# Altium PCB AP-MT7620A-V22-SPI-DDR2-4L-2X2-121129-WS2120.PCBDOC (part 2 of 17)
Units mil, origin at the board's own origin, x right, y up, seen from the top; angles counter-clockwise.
Board outline 7316 x 4279 mil, 4 copper layers (Top, Inner Layer 2, Inner Layer 3, Bottom), stack 35.4 mil thick; 640 components, 473 nets, 2041 pads, 2358 vias.
Unrouted connection lines stored in the file: 11.
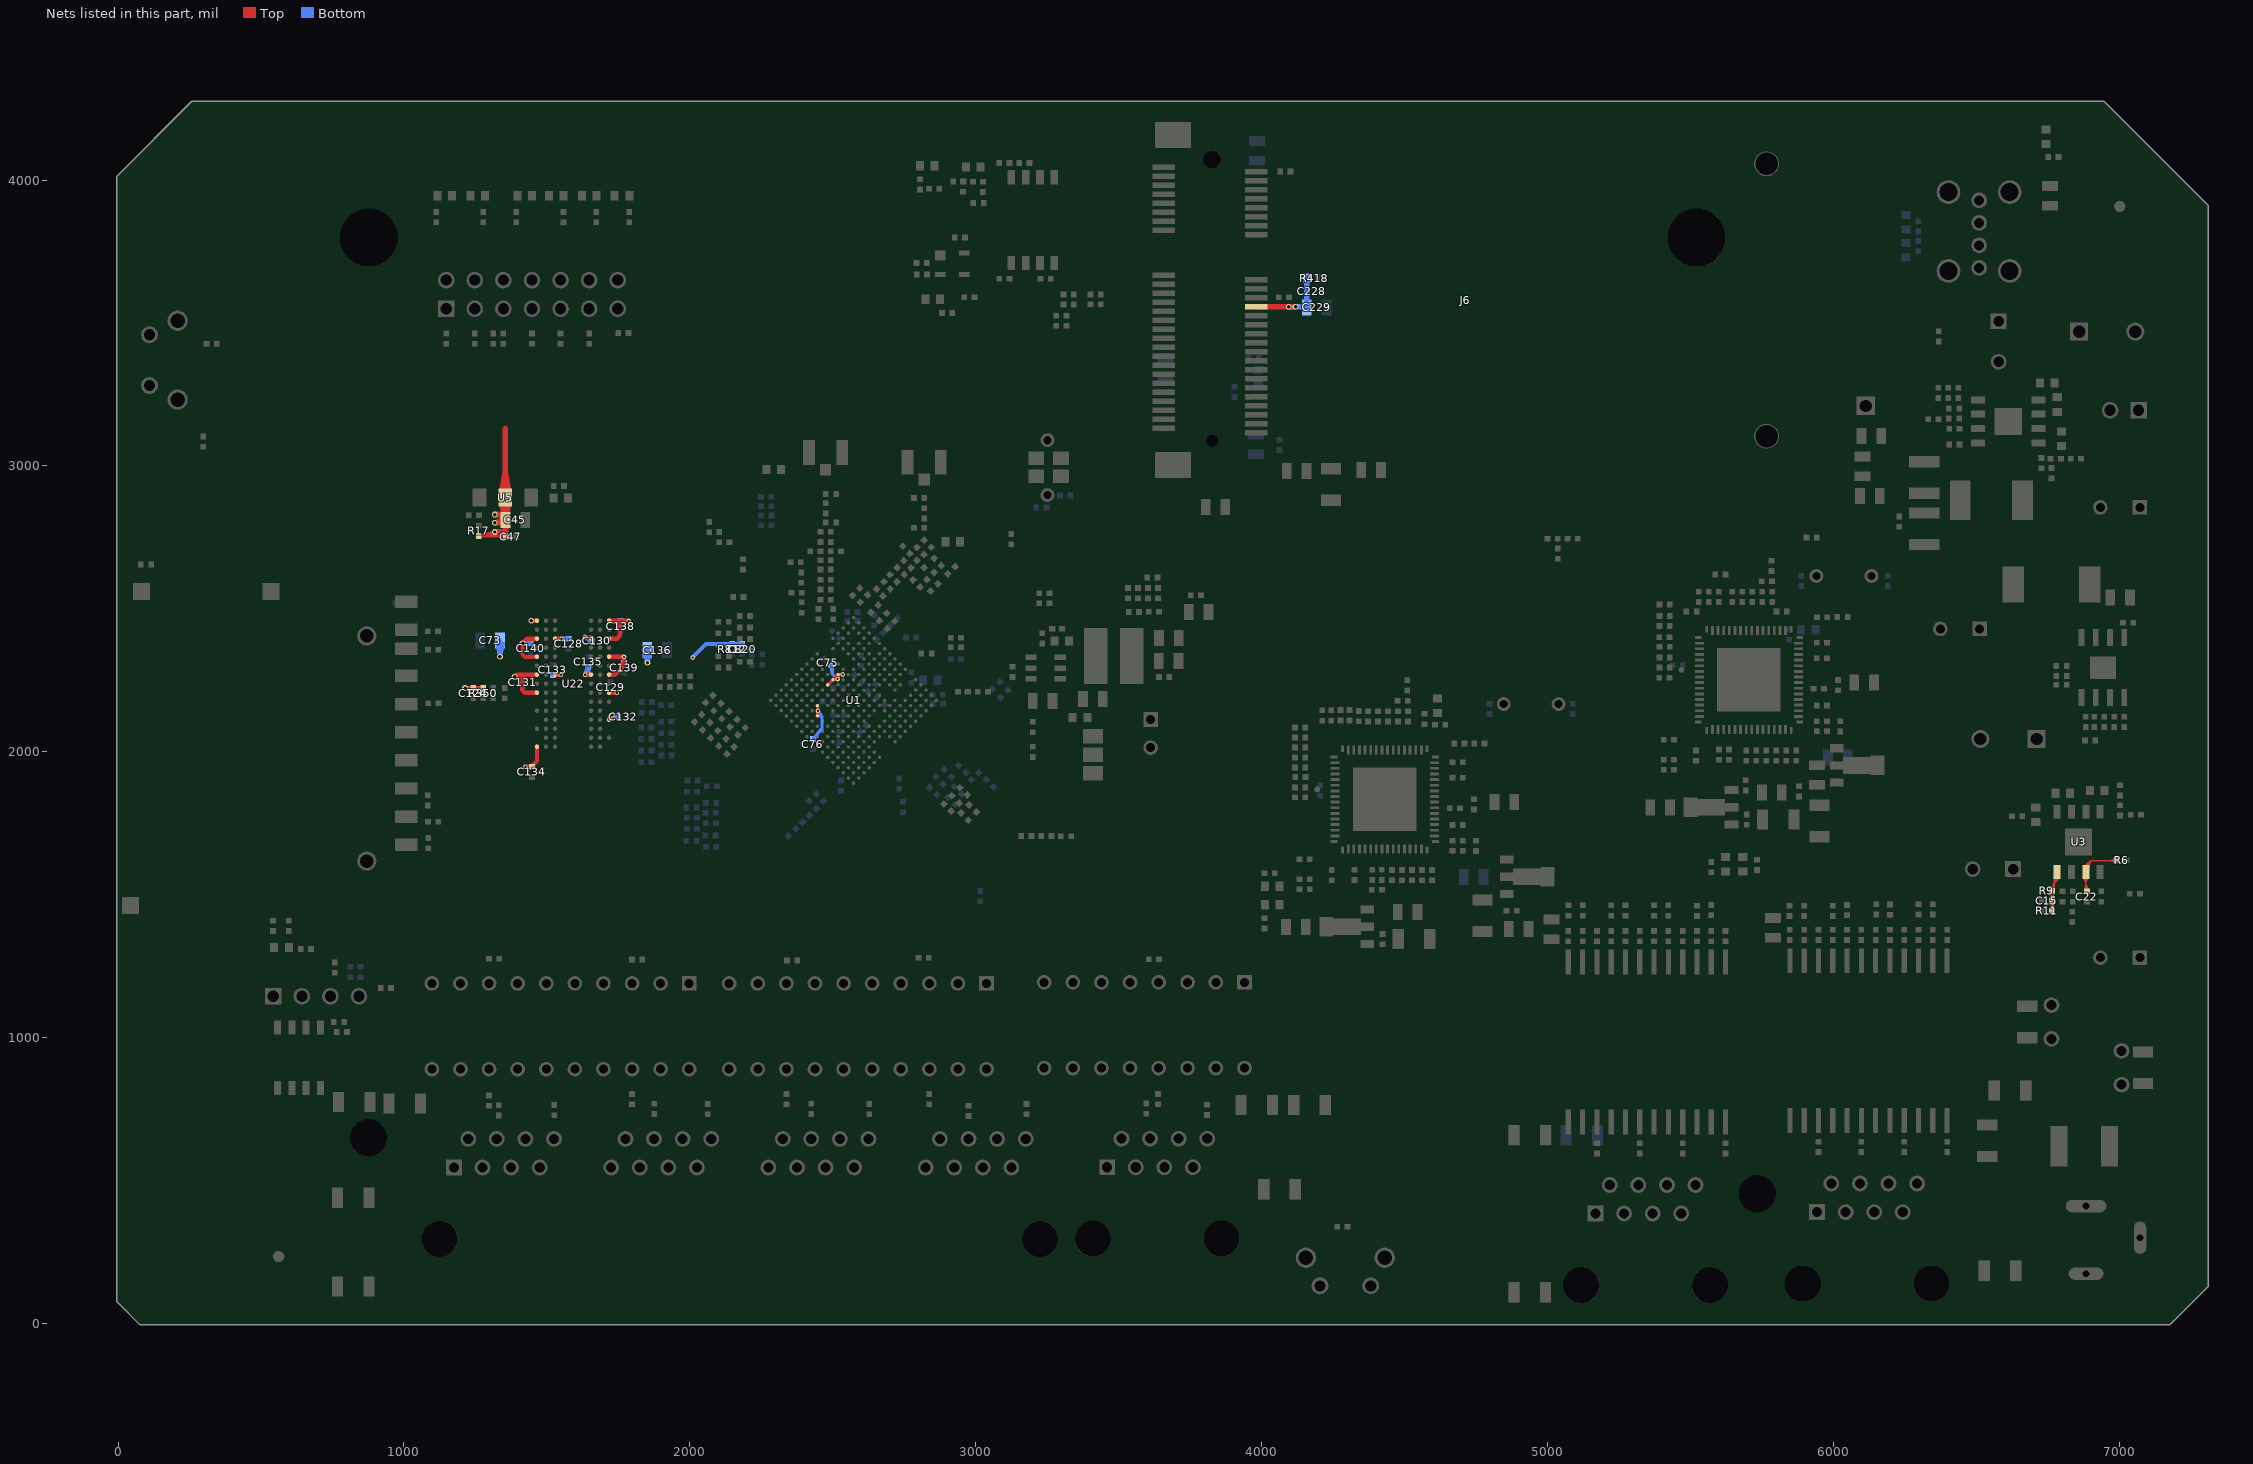
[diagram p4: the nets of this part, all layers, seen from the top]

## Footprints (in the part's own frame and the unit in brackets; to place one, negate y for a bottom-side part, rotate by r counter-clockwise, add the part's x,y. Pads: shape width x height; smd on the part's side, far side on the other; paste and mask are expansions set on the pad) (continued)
CON10P/SMD/R/F/7SDCN-B0-1X14 [mm]
  rect 1.1x2 smd: 1(-2.5,0) 2(-5,0) 3(-7.5,0) 4(-10,0) 5(-12.5,0) 6(-15,0) 7(-17.4,0) 8(-19.1,0) 9(0,0) CD(-21.6,0)
  rect 1.5x1.5 smd: GND1(-22.5,-12) GND2(5.4,-24.5) WP(-22.5,-23.5)
  round 1.7 hole 1.2 unplated: H1(-18.55,-3.5) H2(1.45,-3.5)
  silkscreen extent -22.95,-25.6 5.65,0.1
CRYS/DIP/D5X10.6/GB2000025/ECERA [mm]
  round 1.23 hole 0.73: 1(-2.44,0) 2(2.44,0)
  silkscreen extent -5.79,-2.62 5.79,2.62
CRYS/SMD/D3.2X2.5/E3SB40/HOSONIC [mm]
  rect 1.4x1.2 smd: 1(-1.1,-0.8) 2(1.1,-0.8) 3(1.1,0.8) 4(-1.1,0.8)
  silkscreen extent -2,-1.6 1.7,1.35
D/SMD/P6.61/B540C [mm]
  rect 1.92x3.18 smd: 1(-3.405,0) 2(3.405,0)
  silkscreen extent -3.55,-3.21 3.55,3.21
DC-JACK/3P/DIP/R/JD003-PF [mm]
  oval 3.1x1.1 hole 0.6 slot 2.6 at 0 deg: 1(0,-6)
  oval 1.1x2.9 hole 0.6 slot 2.4 at 0 deg: 2(4.8,-2.8)
  oval 3.6x1.1 hole 0.6 slot 3.1 at 0 deg: 3(0,0)
  silkscreen extent -4.6,-13.9 4.6,0.8
DIP2/P2.54 [mil]
  rect 58x58 hole 39: 1(0,0)
  round 58 hole 39: 2(100,0)
  silkscreen extent -60,-50 150,60
DIP4/P2.54 [mil]
  rect 58x58 hole 39: 1(0,0)
  round 58 hole 39: 2(100,0) 3(200,0) 4(300,0)
  silkscreen extent -60,-50 350,60
DIP7X2/P2.54 [mil]
  rect 58x58 hole 39: 1(0,0)
  round 58 hole 39: 2(0,100) 3(100,0) 4(100,100) 5(200,0) 6(200,100) 7(300,0) 8(300,100) 9(400,0) 10(400,100) 11(500,0) 12(500,100) 13(600,0) 14(600,100)
  silkscreen extent -50,-60 650,160
FD [mm]
  round 1 smd: 1(0,0)
  Top pour cut-out: 1.169,0 1.167,0.057 1.163,0.115 1.156,0.171 1.146,0.228 1.134,0.284 1.118,0.339 1.1,0.394 1.08,0.447 1.057,0.5 1.031,0.551 1.002,0.601 0.972,0.649 0.939,0.696 0.903,0.741 0.866,0.785 0.826,0.826 0.785,0.866 0.741,0.903 0.696,0.939 0.649,0.972 0.601,1.002 0.551,1.031 0.5,1.057 0.447,1.08 0.394,1.1 0.339,1.118 0.284,1.134 0.228,1.146 0.171,1.156 0.115,1.163 0.057,1.167 0,1.169 -0.057,1.167 -0.115,1.163 -0.171,1.156 -0.228,1.146 -0.284,1.134 -0.339,1.118 -0.394,1.1 -0.447,1.08 -0.5,1.057 -0.551,1.031 -0.601,1.002 -0.649,0.972 -0.696,0.939 -0.741,0.903 -0.785,0.866 -0.826,0.826 -0.866,0.785 -0.903,0.741 -0.939,0.696 -0.972,0.649 -1.002,0.601 -1.031,0.551 -1.057,0.5 -1.08,0.447 -1.1,0.394 -1.118,0.339 -1.134,0.284 -1.146,0.228 -1.156,0.171 -1.163,0.115 -1.167,0.057 -1.169,0 -1.167,-0.057 -1.163,-0.115 -1.156,-0.171 -1.146,-0.228 -1.134,-0.284 -1.118,-0.339 -1.1,-0.394 -1.08,-0.447 -1.057,-0.5 -1.031,-0.551 -1.002,-0.601 -0.972,-0.649 -0.939,-0.696 -0.903,-0.741 -0.866,-0.785 -0.826,-0.826 -0.785,-0.866 -0.741,-0.903 -0.696,-0.939 -0.649,-0.972 -0.601,-1.002 -0.551,-1.031 -0.5,-1.057 -0.447,-1.08 -0.394,-1.1 -0.339,-1.118 -0.284,-1.134 -0.228,-1.146 -0.171,-1.156 -0.115,-1.163 -0.057,-1.167 0,-1.169 0.057,-1.167 0.115,-1.163 0.171,-1.156 0.228,-1.146 0.284,-1.134 0.339,-1.118 0.394,-1.1 0.447,-1.08 0.5,-1.057 0.551,-1.031 0.601,-1.002 0.649,-0.972 0.696,-0.939 0.741,-0.903 0.785,-0.866 0.826,-0.826 0.866,-0.785 0.903,-0.741 0.939,-0.696 0.972,-0.649 1.002,-0.601 1.031,-0.551 1.057,-0.5 1.08,-0.447 1.1,-0.394 1.118,-0.339 1.134,-0.284 1.146,-0.228 1.156,-0.171 1.163,-0.115 1.167,-0.057 1.169,0
L0402 [mil]
  rect 20x20 smd: 1(-18,0) 2(18,0)
  silkscreen extent -33,-15 33,15
L0805 [mil]
  rect 34x56 smd: 1(-34.45,0) 2(34.45,0)
  silkscreen extent -63,-38 63,38
L1206 [mm]
  rect 1x1.8 smd: 1(-1.4,0) 2(1.4,0)
  silkscreen extent -2.2,-1.2 2.2,1.2
L/IND/DIP/D6H14 [mil]
  round 55 hole 35: 1(-59.06,0) 2(59.06,0)
  Keep-Out Layer pour cut-out: 202 vertices and 0 holes, not listed, extent -116.12,-118.12 120.12,118.12
  silkscreen extent -118,-123 121,123
L/IND/DIP/MCD-0808-150MU-J [mm]
  rect 1.6x1.6 hole 1.1: 1(-2.5,0)
  round 1.6 hole 1.1: 2(2.5,0)
  silkscreen extent -5.35,-5.35 5.35,5.35
L/IND/SMD/GSTD6030PW-6R8M [mm]
  rect 1.85x3.5 smd: 1(-2.775,0) 2(2.775,0)
  silkscreen extent -3.55,-3.55 3.55,3.45
L/IND/SMD/LVS5045 [mm]
  rect 2.1x5 smd: 1(-1.6,0) 2(1.6,0)
  Top pour cut-out: -0.556,2.507 0.551,2.507 0.551,-2.504 -0.556,-2.504 -0.556,2.507
  silkscreen extent -2.6,-2.6 2.6,2.6
MINI-PCI-EXPRESS/52P/SMD/R/F/C1720007 [mm]
  rect 0.5x2 smd: 1(0,0) 2(0.4,8.2) 3(0.8,0) 4(1.2,8.2) 5(1.6,0) 6(2,8.2) 7(2.4,0) 8(2.8,8.2) 9(3.2,0) 10(3.6,8.2) 11(4,0) 12(4.4,8.2) 13(4.8,0) 14(5.2,8.2) 15(5.6,0) 16(6,8.2) 17(9.6,0) 18(10,8.2) 19(10.4,0) 20(10.8,8.2) 21(11.2,0) 22(11.6,8.2) 23(12,0) 24(12.4,8.2) 25(12.8,0) 26(13.2,8.2) 27(13.6,0) 28(14,8.2) 29(14.4,0) 30(14.8,8.2) 31(15.2,0) 32(15.6,8.2) 33(16,0) 34(16.4,8.2) 35(16.8,0) 36(17.2,8.2) 37(17.6,0) 38(18,8.2) 39(18.4,0) 40(18.8,8.2) 41(19.2,0) 42(19.6,8.2) 43(20,0) 44(20.4,8.2) 45(20.8,0) 46(21.2,8.2) 47(21.6,0) 48(22,8.2) 49(22.4,0) 50(22.8,8.2) 51(23.2,0) 52(23.6,8.2)
  rect 2.3x3.2 smd: 53(-2.85,0.8) 54(26.45,0.8)
  round 1.6 hole 1.6 unplated: 55(-0.7,4.3)
  round 1.1 hole 1.1 unplated: 56(24.3,4.3)
  round 2.2 hole 2: 57(-0.3,53.55)
  round 2.2 / inner round 2.2 / far side round 2 hole 2: 58(23.9,53.55)
  Top region: -3.2,49.454 2.515,49.454 2.515,55.397 21.082,55.397 21.082,49.454 26.822,49.454 26.822,59.741 15.824,59.741 15.824,57.252 13.564,57.252 13.564,59.741 10.033,59.741 10.033,57.252 7.747,57.252 7.747,59.741 -3.2,59.741 -3.2,49.454
  Keep-Out Layer pour cut-out: 25.104,4.3 25.103,4.349 25.098,4.397 25.091,4.445 25.081,4.492 25.068,4.539 25.052,4.585 25.034,4.63 25.012,4.674 24.988,4.716 24.962,4.757 24.933,4.796 24.902,4.833 24.869,4.869 24.833,4.902 24.796,4.933 24.757,4.962 24.716,4.988 24.674,5.012 24.63,5.034 24.585,5.052 24.539,5.068 24.492,5.081 24.445,5.091 24.397,5.098 24.349,5.103 24.3,5.104 24.251,5.103 24.203,5.098 24.155,5.091 24.108,5.081 24.061,5.068 24.015,5.052 23.97,5.034 23.926,5.012 23.884,4.988 23.843,4.962 23.804,4.933 23.767,4.902 23.731,4.869 23.698,4.833 23.667,4.796 23.638,4.757 23.612,4.716 23.588,4.674 23.566,4.63 23.548,4.585 23.532,4.539 23.519,4.492 23.509,4.445 23.501,4.397 23.497,4.349 23.496,4.3 23.497,4.251 23.501,4.203 23.509,4.155 23.519,4.108 23.532,4.061 23.548,4.015 23.566,3.97 23.588,3.926 23.612,3.884 23.638,3.843 23.667,3.804 23.698,3.767 23.731,3.731 23.767,3.698 23.804,3.667 23.843,3.638 23.884,3.612 23.926,3.588 23.97,3.566 24.015,3.548 24.061,3.532 24.108,3.519 24.155,3.509 24.203,3.501 24.251,3.497 24.3,3.496 24.349,3.497 24.397,3.501 24.445,3.509 24.492,3.519 24.539,3.532 24.585,3.548 24.63,3.566 24.674,3.588 24.716,3.612 24.757,3.638 24.796,3.667 24.833,3.698 24.869,3.731 24.902,3.767 24.933,3.804 24.962,3.843 24.988,3.884 25.012,3.926 25.034,3.97 25.052,4.015 25.068,4.061 25.081,4.108 25.091,4.155 25.098,4.203 25.103,4.251 25.104,4.3
  Keep-Out Layer pour cut-out: 0.354,4.3 0.353,4.355 0.349,4.41 0.341,4.465 0.331,4.519 0.318,4.573 0.303,4.626 0.284,4.678 0.263,4.729 0.239,4.779 0.213,4.827 0.184,4.874 0.153,4.92 0.119,4.964 0.084,5.006 0.046,5.046 0.006,5.084 -0.036,5.119 -0.08,5.153 -0.126,5.184 -0.173,5.213 -0.221,5.239 -0.271,5.263 -0.322,5.284 -0.374,5.303 -0.427,5.318 -0.481,5.331 -0.535,5.341 -0.59,5.349 -0.645,5.353 -0.7,5.354 -0.755,5.353 -0.81,5.349 -0.865,5.341 -0.919,5.331 -0.973,5.318 -1.026,5.303 -1.078,5.284 -1.129,5.263 -1.179,5.239 -1.227,5.213 -1.274,5.184 -1.32,5.153 -1.364,5.119 -1.406,5.084 -1.446,5.046 -1.484,5.006 -1.519,4.964 -1.553,4.92 -1.584,4.874 -1.613,4.827 -1.639,4.779 -1.663,4.729 -1.684,4.678 -1.703,4.626 -1.718,4.573 -1.731,4.519 -1.741,4.465 -1.749,4.41 -1.753,4.355 -1.754,4.3 -1.753,4.245 -1.749,4.19 -1.741,4.135 -1.731,4.081 -1.718,4.027 -1.703,3.974 -1.684,3.922 -1.663,3.871 -1.639,3.821 -1.613,3.773 -1.584,3.726 -1.553,3.68 -1.519,3.636 -1.484,3.594 -1.446,3.554 -1.406,3.516 -1.364,3.481 -1.32,3.447 -1.274,3.416 -1.227,3.387 -1.179,3.361 -1.129,3.337 -1.078,3.316 -1.026,3.297 -0.973,3.282 -0.919,3.269 -0.865,3.259 -0.81,3.251 -0.755,3.247 -0.7,3.246 -0.645,3.247 -0.59,3.251 -0.535,3.259 -0.481,3.269 -0.427,3.282 -0.374,3.297 -0.322,3.316 -0.271,3.337 -0.221,3.361 -0.173,3.387 -0.126,3.416 -0.08,3.447 -0.036,3.481 0.006,3.516 0.046,3.554 0.084,3.594 0.119,3.636 0.153,3.68 0.184,3.726 0.213,3.773 0.239,3.821 0.263,3.871 0.284,3.922 0.303,3.974 0.318,4.027 0.331,4.081 0.341,4.135 0.349,4.19 0.353,4.245 0.354,4.3
  silkscreen extent -4.5,-1.7 28,60.2
MT7620AE2/TFBGA265/P0.65/B0.3/11X11 [mm]
  round 0.3 smd: A1(-5.2,5.2) A2(-4.55,5.2) A3(-3.9,5.2) A4(-3.25,5.2) A5(-2.6,5.2) A6(-1.95,5.2) A7(-1.3,5.2) A8(-0.65,5.2) A9(0,5.2) A10(0.65,5.2) A11(1.3,5.2) A13(2.6,5.2) A14(3.25,5.2) A15(3.9,5.2) A16(4.55,5.2) A17(5.2,5.2) B1(-5.2,4.55) B2(-4.55,4.55) B3(-3.9,4.55) B4(-3.25,4.55) B5(-2.6,4.55) B7(-1.3,4.55) B8(-0.65,4.55) B9(0,4.55) B10(0.65,4.55) B11(1.3,4.55) B14(3.25,4.55) B15(3.9,4.55) B16(4.55,4.55) B17(5.2,4.55) C1(-5.2,3.9) C2(-4.55,3.9) C4(-3.25,3.9) C5(-2.6,3.9) C6(-1.95,3.9) C7(-1.3,3.9) C8(-0.65,3.9) C9(0,3.9) C10(0.65,3.9) C11(1.3,3.9) C12(1.95,3.9) C14(3.25,3.9) C15(3.9,3.9) C16(4.55,3.9) C17(5.2,3.9) D1(-5.2,3.25) D2(-4.55,3.25) D3(-3.9,3.25) D4(-3.25,3.25) D5(-2.6,3.25) D6(-1.95,3.25) D7(-1.3,3.25) D8(-0.65,3.25) D9(0,3.25) D10(0.65,3.25) D11(1.3,3.25) D12(1.95,3.25) D14(3.25,3.25) D15(3.9,3.25) D16(4.55,3.25) D17(5.2,3.25) E1(-5.2,2.6) E2(-4.55,2.6) E3(-3.9,2.6) E4(-3.25,2.6) E5(-2.6,2.6) E6(-1.95,2.6) E7(-1.3,2.6) E8(-0.65,2.6) E9(0,2.6) E10(0.65,2.6) E13(2.6,2.6) E14(3.25,2.6) E15(3.9,2.6) E16(4.55,2.6) E17(5.2,2.6) F2(-4.55,1.95) F6(-1.95,1.95) F7(-1.3,1.95) F8(-0.65,1.95) F9(0,1.95) F10(0.65,1.95) F11(1.3,1.95) F12(1.95,1.95) F13(2.6,1.95) F14(3.25,1.95) F15(3.9,1.95) F16(4.55,1.95) F17(5.2,1.95) G4(-3.25,1.3) G5(-2.6,1.3) G6(-1.95,1.3) G7(-1.3,1.3) G8(-0.65,1.3) G9(0,1.3) G10(0.65,1.3) G11(1.3,1.3) G12(1.95,1.3) G13(2.6,1.3) G14(3.25,1.3) G15(3.9,1.3) G16(4.55,1.3) G17(5.2,1.3) H1(-5.2,0.65) H2(-4.55,0.65) H3(-3.9,0.65) H4(-3.25,0.65) H5(-2.6,0.65) H6(-1.95,0.65) H7(-1.3,0.65) H8(-0.65,0.65) H9(0,0.65) H10(0.65,0.65) H11(1.3,0.65) H12(1.95,0.65) H14(3.25,0.65) H15(3.9,0.65) H16(4.55,0.65) H17(5.2,0.65) J1(-5.2,0) J2(-4.55,0) J3(-3.9,0) J4(-3.25,0) J5(-2.6,0) J6(-1.95,0) J7(-1.3,0) J8(-0.65,0) J9(0,0) J10(0.65,0) J11(1.3,0) J12(1.95,0) J14(3.25,0) J15(3.9,0) J16(4.55,0) J17(5.2,0) K1(-5.2,-0.65) K2(-4.55,-0.65) K3(-3.9,-0.65) K4(-3.25,-0.65) K5(-2.6,-0.65) K6(-1.95,-0.65) K7(-1.3,-0.65) K8(-0.65,-0.65) K9(0,-0.65) K10(0.65,-0.65) K11(1.3,-0.65) K12(1.95,-0.65) K13(2.6,-0.65) K14(3.25,-0.65) K15(3.9,-0.65) L1(-5.2,-1.3) L2(-4.55,-1.3) L3(-3.9,-1.3) L4(-3.25,-1.3) L5(-2.6,-1.3) L6(-1.95,-1.3) L7(-1.3,-1.3) L8(-0.65,-1.3) L9(0,-1.3) L10(0.65,-1.3) L11(1.3,-1.3) L12(1.95,-1.3) L13(2.6,-1.3) L14(3.25,-1.3) L15(3.9,-1.3) M1(-5.2,-1.95) M2(-4.55,-1.95) M3(-3.9,-1.95) M4(-3.25,-1.95) M5(-2.6,-1.95) M6(-1.95,-1.95) M7(-1.3,-1.95) M8(-0.65,-1.95) M9(0,-1.95) M10(0.65,-1.95) M11(1.3,-1.95) M12(1.95,-1.95) M13(2.6,-1.95) M14(3.25,-1.95) M15(3.9,-1.95) M16(4.55,-1.95) M17(5.2,-1.95) N1(-5.2,-2.6) N2(-4.55,-2.6) N3(-3.9,-2.6) N4(-3.25,-2.6) N5(-2.6,-2.6) N6(-1.95,-2.6) N9(0,-2.6) N10(0.65,-2.6) N11(1.3,-2.6) N12(1.95,-2.6) N13(2.6,-2.6) N14(3.25,-2.6) N15(3.9,-2.6) N16(4.55,-2.6) N17(5.2,-2.6) P1(-5.2,-3.25) P2(-4.55,-3.25) P3(-3.9,-3.25) P4(-3.25,-3.25) P5(-2.6,-3.25) P6(-1.95,-3.25) P7(-1.3,-3.25) P8(-0.65,-3.25) P9(0,-3.25) P10(0.65,-3.25) P11(1.3,-3.25) P12(1.95,-3.25) P13(2.6,-3.25) P14(3.25,-3.25) P15(3.9,-3.25) P16(4.55,-3.25) P17(5.2,-3.25) R1(-5.2,-3.9) R2(-4.55,-3.9) R3(-3.9,-3.9) R4(-3.25,-3.9) R5(-2.6,-3.9) R6(-1.95,-3.9) R7(-1.3,-3.9) R8(-0.65,-3.9) R9(0,-3.9) R10(0.65,-3.9) R11(1.3,-3.9) R12(1.95,-3.9) R13(2.6,-3.9) R14(3.25,-3.9) R15(3.9,-3.9) R16(4.55,-3.9) R17(5.2,-3.9) T1(-5.2,-4.55) T2(-4.55,-4.55) T3(-3.9,-4.55) T4(-3.25,-4.55) T5(-2.6,-4.55) T6(-1.95,-4.55) T7(-1.3,-4.55) T8(-0.65,-4.55) T9(0,-4.55) T10(0.65,-4.55) T11(1.3,-4.55) T12(1.95,-4.55) T13(2.6,-4.55) T14(3.25,-4.55) T15(3.9,-4.55) T16(4.55,-4.55) T17(5.2,-4.55) U1(-5.2,-5.2) U2(-4.55,-5.2) U3(-3.9,-5.2) U4(-3.25,-5.2) U5(-2.6,-5.2) U6(-1.95,-5.2) U7(-1.3,-5.2) U8(-0.65,-5.2) U9(0,-5.2) U10(0.65,-5.2) U11(1.3,-5.2) U12(1.95,-5.2) U13(2.6,-5.2) U14(3.25,-5.2) U15(3.9,-5.2) U16(4.55,-5.2) U17(5.2,-5.2)
  silkscreen extent -6,-5.6 5.6,6
O130 [mil]
  round 130 hole 130 unplated: 1(0,0)
  Keep-Out Layer pour cut-out: 162 vertices and 0 holes, not listed, extent -75.01,-75.01 75.01,75.01
O200 [mil]
  round 203 hole 203 unplated: 1(0,0)
  Keep-Out Layer pour cut-out: 194 vertices and 0 holes, not listed, extent -111.43,-111.43 111.43,111.43
P1//M [mil]
  rect 65x65 hole 43: 1(0,0)
  silkscreen extent -50,-50 50,50
PAD/1P/0.5MM [mil]
  round 20 smd: 1(-0.39,0.26)
  silkscreen extent -15,-15 15,15
QFN64/SMD/P0.5/IP1001 [mm]
  rect 0.25x0.6 smd: 1(-3.75,-4.5) 16(3.75,-4.5) 33(3.75,4.5) 48(-3.75,4.5)
  rect 0.25x0.8 smd: 2(-3.25,-4.4) 3(-2.75,-4.4) 4(-2.25,-4.4) 5(-1.75,-4.4) 6(-1.25,-4.4) 7(-0.75,-4.4) 8(-0.25,-4.4) 9(0.25,-4.4) 10(0.75,-4.4) 11(1.25,-4.4) 12(1.75,-4.4) 13(2.25,-4.4) 14(2.75,-4.4) 15(3.25,-4.4) 34(3.25,4.4) 35(2.75,4.4) 36(2.25,4.4) 37(1.75,4.4) 38(1.25,4.4) 39(0.75,4.4) 40(0.25,4.4) 41(-0.25,4.4) 42(-0.75,4.4) 43(-1.25,4.4) 44(-1.75,4.4) 45(-2.25,4.4) 46(-2.75,4.4) 47(-3.25,4.4)
  rect 0.6x0.25 smd: 17(4.5,-3.75) 32(4.5,3.75) 49(-4.5,3.75) 64(-4.5,-3.75)
  rect 0.8x0.25 smd: 18(4.4,-3.25) 19(4.4,-2.75) 20(4.4,-2.25) 21(4.4,-1.75) 22(4.4,-1.25) 23(4.4,-0.75) 24(4.4,-0.25) 25(4.4,0.25) 26(4.4,0.75) 27(4.4,1.25) 28(4.4,1.75) 29(4.4,2.25) 30(4.4,2.75) 31(4.4,3.25) 50(-4.4,3.25) 51(-4.4,2.75) 52(-4.4,2.25) 53(-4.4,1.75) 54(-4.4,1.25) 55(-4.4,0.75) 56(-4.4,0.25) 57(-4.4,-0.25) 58(-4.4,-0.75) 59(-4.4,-1.25) 60(-4.4,-1.75) 61(-4.4,-2.25) 62(-4.4,-2.75) 63(-4.4,-3.25)
  rect 5.64x5.64 smd: 65(0,0)
  Top pour cut-out: -3.998,3.877 -3.998,-3.88 -4.806,-3.88 -4.806,3.877 -3.998,3.877
  Top pour cut-out: 4.798,3.88 4.798,-3.872 3.993,-3.872 3.993,3.88 4.798,3.88
  Top pour cut-out: 3.87,-4.794 -3.882,-4.794 -3.882,-3.993 3.87,-3.993 3.87,-4.794
  Top pour cut-out: 3.876,4 -3.876,4 -3.876,4.802 3.876,4.802 3.876,4
  silkscreen extent -5.8,-5.8 5.8,5.8
R0402 [mil]
  rect 20x20 smd: 1(-18,0) 2(18,0)
  silkscreen extent -33,-15 33,15
R0603 [mil]
  rect 28x32 smd: 1(-25.59,0) 2(25.59,0)
  silkscreen extent -48,-25 48,25
R0805 [mil]
  rect 34x56 smd: 1(-34.45,0) 2(34.45,0)
  silkscreen extent -62,-38 63,38
RJ45/8P/DIP/R/8208C-B01 [mm]
  rect 1.4x1.4 / inner round 1.4 / far side rect 1.4x1.4 hole 0.9: 1(0,0)
  round 1.4 hole 0.9: 2(1.27,2.54) 3(2.54,0) 4(3.81,2.54) 5(5.08,0) 6(6.35,2.54) 7(7.62,0) 8(8.89,2.54)
  round 3.2 hole 3.2 unplated: 9(-1.27,-6.35) 10(10.16,-6.35)
  Keep-Out Layer pour cut-out: 154 vertices and 0 holes, not listed, extent 8.306,-8.204 12.014,-4.496
  Keep-Out Layer pour cut-out: 154 vertices and 0 holes, not listed, extent -3.124,-8.204 0.584,-4.496
  silkscreen extent -3.25,-16.9 12.14,3.8
RJ45/8P/DIP/R/N3612-002 [mm]
  rect 1.4x1.4 / inner round 1.4 / far side rect 1.4x1.4 hole 0.9: 1(0,0)
  round 1.4 hole 0.9: 2(1.27,2.54) 3(2.54,0) 4(3.81,2.54) 5(5.08,0) 6(6.35,2.54) 7(7.62,0) 8(8.89,2.54)
  round 3.2 hole 3.2 unplated: 9(-1.27,-6.35) 10(10.16,-6.35)
  Keep-Out Layer pour cut-out: 154 vertices and 0 holes, not listed, extent 8.326,-8.204 12.034,-4.496
  Keep-Out Layer pour cut-out: 154 vertices and 0 holes, not listed, extent -3.104,-8.204 0.604,-4.496
  silkscreen extent -3.25,-13.95 12.14,3.85
RJ45/32P/DIP/R/N3642-001 [mm]
  rect 1.4x1.4 / inner round 1.4 / far side round 1.4 hole 0.9: 1(0,0)
  round 1.4 hole 0.9: 2(1.27,2.54) 3(2.54,0) 4(3.81,2.54) 5(5.08,0) 6(6.35,2.54) 7(7.62,0) 8(8.89,2.54) 9(13.97,0) 10(15.24,2.54) 11(16.51,0) 12(17.78,2.54) 13(19.05,0) 14(20.32,2.54) 15(21.59,0) 16(22.86,2.54) 17(27.94,0) 18(29.21,2.54) 19(30.48,0) 20(31.75,2.54) 21(33.02,0) 22(34.29,2.54) 23(35.56,0) 24(36.83,2.54) 25(41.91,0) 26(43.18,2.54) 27(44.45,0) 28(45.72,2.54) 29(46.99,0) 30(48.26,2.54) 31(49.53,0) 32(50.8,2.54)
  round 3.2 hole 3.2 unplated: 33(-1.27,-6.35) 34(52.07,-6.35)
  Keep-Out Layer pour cut-out: 154 vertices and 0 holes, not listed, extent 50.216,-8.204 53.924,-4.496
  Keep-Out Layer pour cut-out: 154 vertices and 0 holes, not listed, extent -3.124,-8.204 0.584,-4.496
  silkscreen extent -3.9,-13.95 54.7,3.85
SB/0402 [mil]
  rect 22x20 smd: 1(-17,0) 2(17,0)
  Top region: 28,-10 0,-10 0,10 28,10 28,-10
  Top region: -28,10 0,10 0,-10 -28,-10 -28,10
  silkscreen extent -33,-15 33,15
SB/0603 [mil]
  rect 28x32 smd: 1(-25.59,0) 2(25.59,0)
  Top region: -39.6,16 0,16 0,-16 -39.6,-16 -39.6,16
  Top region: 0,16 39.6,16 39.6,-16 0,-16 0,16
  silkscreen extent -48,-25 48,25
SB/1206 [mm]
  rect 1x1.8 smd: 1(-1.4,0) 2(1.4,0)
  Top region: 0,-0.9 1.9,-0.9 1.9,0.9 0,0.9 0,-0.9
  Top region: -1.9,0.9 0,0.9 0,-0.9 -1.9,-0.9 -1.9,0.9
  silkscreen extent -2.2,-1.2 2.2,1.2
SOIC8/SMD/P1.27/AT24C04B-08B [mm]
  rect 0.61x1.235 smd: 1(-1.905,-2.68) 2(-0.635,-2.68) 3(0.635,-2.68) 4(1.905,-2.68) 5(1.905,2.68) 6(0.635,2.68) 7(-0.635,2.68) 8(-1.905,2.68)
  silkscreen extent -2.97,-2.49 2.5,2
SOIC8/SMD/P1.27/AT26DF321 [mm]
  rect 0.68x1.25 smd: 1(-1.905,-3.805) 2(-0.635,-3.805) 3(0.635,-3.805) 4(1.905,-3.805) 5(1.905,3.805) 6(0.635,3.805) 7(-0.635,3.805) 8(-1.905,3.805)
  silkscreen extent -3.13,-3.17 2.73,2.75
SOP8/SMD/P1.27/IT7653 [mm]
  rect 0.62x1.235 smd: 1(-1.905,-2.682) 2(-0.635,-2.682) 3(0.635,-2.682) 4(1.905,-2.682) 5(1.905,2.682) 6(0.635,2.682) 7(-0.635,2.682) 8(-1.905,2.682)
  rect 2.41x2.41 smd: 9(0,0)
  Top region: -1.65,1.205 1.65,1.205 1.65,-1.205 -1.65,-1.205 -1.65,1.205
  silkscreen extent -2.85,-2.38 2.5,2
SOP8/SMD/P1.27/RT8251 [mm]
  rect 0.51x1.5 smd: 1(-1.905,-2.65) 2(-0.635,-2.65) 3(0.635,-2.65) 4(1.905,-2.65) 5(1.905,2.65) 6(0.635,2.65) 7(-0.635,2.65) 8(-1.905,2.65)
  rect 2.3x2 smd: 9(0,0)
  silkscreen extent -3.1,-2.72 2.6,2.1
SOT89/SMD [mil]
  rect 50x70 smd: 1(-65,0) 2(0,0) 3(65,0)
  Top region: 25,-35 25,50 50,75 50,150 35,165 -35,165 -50,150 -50,75 -25,50 -25,-35 25,-35
  silkscreen extent -100,-45 100,175
SOT223-3/SMD/P2.3/AX1007 [mm]
  rect 1.2x1.6 smd: 1(-2.3,-3.2) 2(0,-3.2) 3(2.3,-3.2)
  Top region: -1.65,4.15 1.65,4.15 1.65,2.25 -1.65,2.25 -1.65,4.15
  silkscreen extent -3.65,-2.15 3.4,1.9
SOT-23-6/SMD/P0.95/APM2701AC [mm]
  rect 0.5x1 smd: 1(-0.95,-1.3) 2(0,-1.3) 3(0.95,-1.3) 4(0.95,1.3) 5(0,1.3) 6(-0.95,1.3)
  silkscreen extent -1.9,-1.25 1.65,1
SOT-89/SMD/2SB1386 [mm]
  rect 0.72x1.225 smd: 1(-1.52,-1.813) 3(1.52,-1.813) 4(0,-1.813)
  rect 1.75x1.225 smd: 2(0,1.813)
  rect 1.5x2.5 smd: 5(0,0)
  silkscreen extent -2.35,-1.35 2.35,1.35
SOT-143/SMD/G693 [mm]
  rect 0.89x0.95 smd: 1(-0.76,-1.075)
  rect 0.46x0.95 smd: 2(0.96,-1.075) 3(0.96,1.075) 4(-0.96,1.075)
  silkscreen extent -1.92,-1.1 1.62,0.8
SW/4P/DIP/TS02-CN-PF [mm]
  round 1.5 hole 1: 1(-2.25,0) 2(2.25,0)
  round 1.8 hole 1.3: 3(-3.5,2.5) 4(3.5,2.5)
  silkscreen extent -3.75,-5.85 3.75,4.05
TRANSFORMER/16P/DIP/HN1674CG [mm]
  rect 1.3x1.3 / inner round 1.3 / far side round 1.3 hole 0.8: 1(-8.9,-3.81)
  round 1.3 hole 0.8: 2(-6.35,-3.81) 3(-3.843,-3.81) 4(-1.27,-3.81) 5(1.27,-3.81) 6(3.81,-3.81) 7(6.35,-3.81) 8(8.9,-3.81) 9(8.9,3.81) 10(6.35,3.81) 11(3.81,3.81) 12(1.27,3.81) 13(-1.27,3.81) 14(-3.843,3.81) 15(-6.35,3.81) 16(-8.9,3.81)
  silkscreen extent -10.82,-5.61 10.2,5
TRANSFORMER/20P/DIP/HN2066CG [mm]
  rect 1.3x1.3 / inner round 1.3 / far side round 1.3 hole 0.8: 1(-11.43,-3.81)
  round 1.3 hole 0.8: 2(-8.89,-3.81) 3(-6.35,-3.81) 4(-3.81,-3.81) 5(-1.27,-3.81) 6(1.27,-3.81) 7(3.81,-3.81) 8(6.35,-3.81) 9(8.89,-3.81) 10(11.43,-3.81) 11(11.43,3.81) 12(8.89,3.81) 13(6.35,3.81) 14(3.81,3.81) 15(1.27,3.81) 16(-1.27,3.81) 17(-3.81,3.81) 18(-6.35,3.81) 19(-8.89,3.81) 20(-11.43,3.81)
  silkscreen extent -13.34,-5.81 12.7,5.1
TRANSFORMER/24P/SMD/HN2429CG [mm]
  rect 0.46x2.2 smd: 1(-6.985,-7.1) 2(-5.715,-7.1) 3(-4.445,-7.1) 4(-3.175,-7.1) 5(-1.905,-7.1) 6(-0.635,-7.1) 7(0.635,-7.1) 8(1.905,-7.1) 9(3.175,-7.1) 10(4.445,-7.1) 11(5.715,-7.1) 12(6.985,-7.1) 13(6.985,7.1) 14(5.715,7.1) 15(4.445,7.1) 16(3.175,7.1) 17(1.905,7.1) 18(0.635,7.1) 19(-0.635,7.1) 20(-1.905,7.1) 21(-3.175,7.1) 22(-4.445,7.1) 23(-5.715,7.1) 24(-6.985,7.1)
  silkscreen extent -9.68,-6.62 9,5.8
USB/4P/P2.0/DIP/R/F/SUA-110VB-B2N [mm]
  round 1.4 hole 0.9: 1(0,0) 2(-2,0) 3(-4,0) 4(-6,0)
  round 2.1 hole 1.6: 5(0.73,2.72) 6(0.73,-2.72) 7(-6.27,2.72) 8(-6.27,-2.72)
  silkscreen extent -7.44,-3.9 12.33,3.9
VARISTOR/SMD/TVM5B150L103RY [mm]
  rect 1.5x3.6 smd: 1(-2.25,0) 2(2.25,0)
  silkscreen extent -1.35,-1.8 1.35,1.8
WBGA84/SMD/P0.8/W9751G6IB [mm]
  round 0.4 smd: A1(-5.6,-3.2) A2(-5.6,-2.4) A3(-5.6,-1.6) A7(-5.6,1.6) A8(-5.6,2.4) A9(-5.6,3.2) B1(-4.8,-3.2) B2(-4.8,-2.4) B3(-4.8,-1.6) B7(-4.8,1.6) B8(-4.8,2.4) B9(-4.8,3.2) C1(-4,-3.2) C2(-4,-2.4) C3(-4,-1.6) C7(-4,1.6) C8(-4,2.4) C9(-4,3.2) D1(-3.2,-3.2) D2(-3.2,-2.4) D3(-3.2,-1.6) D7(-3.2,1.6) D8(-3.2,2.4) D9(-3.2,3.2) E1(-2.4,-3.2) E2(-2.4,-2.4) E3(-2.4,-1.6) E7(-2.4,1.6) E8(-2.4,2.4) E9(-2.4,3.2) F1(-1.6,-3.2) F2(-1.6,-2.4) F3(-1.6,-1.6) F7(-1.6,1.6) F8(-1.6,2.4) F9(-1.6,3.2) G1(-0.8,-3.2) G2(-0.8,-2.4) G3(-0.8,-1.6) G7(-0.8,1.6) G8(-0.8,2.4) G9(-0.8,3.2) H1(0,-3.2) H2(0,-2.4) H3(0,-1.6) H7(0,1.6) H8(0,2.4) H9(0,3.2) J1(0.8,-3.2) J2(0.8,-2.4) J3(0.8,-1.6) J7(0.8,1.6) J8(0.8,2.4) J9(0.8,3.2) K2(1.6,-2.4) K3(1.6,-1.6) K7(1.6,1.6) K8(1.6,2.4) K9(1.6,3.2) L1(2.4,-3.2) L2(2.4,-2.4) L3(2.4,-1.6) L7(2.4,1.6) L8(2.4,2.4) M2(3.2,-2.4) M3(3.2,-1.6) M7(3.2,1.6) M8(3.2,2.4) M9(3.2,3.2) N1(4,-3.2) N2(4,-2.4) N3(4,-1.6) N7(4,1.6) N8(4,2.4) P2(4.8,-2.4) P3(4.8,-1.6) P7(4.8,1.6) P8(4.8,2.4) P9(4.8,3.2) R1(5.6,-3.2) R2(5.6,-2.4) R3(5.6,-1.6) R7(5.6,1.6) R8(5.6,2.4)
  silkscreen extent -6.85,-5.5 6.85,5.5

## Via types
v1: diameter 20, hole 12, Top to Bottom, 2117 vias
v2: diameter 16, hole 8, Top to Bottom, 241 vias

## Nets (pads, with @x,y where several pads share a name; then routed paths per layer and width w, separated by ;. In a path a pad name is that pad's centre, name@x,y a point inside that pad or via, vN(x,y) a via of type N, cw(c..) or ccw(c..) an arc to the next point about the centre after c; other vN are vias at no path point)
1.8VD: C45.1 C47.1 C73.1 C75.1 C76.1 C124.1 C128.1 C129.1 C130.1 C131.1 C132.1 C133.1 C134.1 C135.1 C136.1 C138.1 C139.1 C140.1 C820.1 R17.1 R350.1 R812.1 U1.H5 U1.J5 U1.K5 U1.N6 U1.P7 U5.2 U22.A1 U22.A9 U22.C1 U22.C3 U22.C7 U22.C9 U22.E1 U22.E9 U22.G1 U22.G3 U22.G7 U22.G9 U22.J1 U22.J9 U22.M9 U22.R1 | length 6051.8
  Top w4: v2@2511.14,2255.79 U1.H5@2517.09,2268.85 ; v2@2511.82,2257.53 U1.H5@2522.59,2270.03 ; v2@2511.85,2257.58 U1.H5@2522.5,2269.53 ; v2@2522.67,2256.45 U1.H5@2514.83,2270.03 ; v2@2522.69,2256.42 U1.H5@2514.81,2270.39 ; v2@2522.87,2255.72 U1.H5@2517.09,2268.85 ; v2@2511.26,2256.24 U1.H5@2518.71,2270.48 ; v2@2511.26,2256.24 U1.H5@2518.71,2270.48 ; v2@2511.26,2256.24 U1.H5@2518.71,2270.48 ; U1.H5@2514.81,2270.39 v2@2517.09,2255.91 ; U1.H5@2514.81,2270.39 2511.01,2254.81 U1.H5@2514.83,2270.03 ; U1.H5@2514.81,2270.39 v2(2517,2254.5) ; U1.H5@2514.83,2270.03 v2@2518.71,2253.29 ; U1.H5@2514.83,2270.03 v2(2517,2254.5) ; v2(2517,2254.5) 2519,2253 v2@2518.71,2253.29 ; v2(2517,2254.5) U1.H5@2517.09,2268.85 ; v2(2517,2254.5) U1.H5@2518.71,2270.48 ; v2(2517,2254.5) U1.H5@2522.5,2269.53 ; v2(2517,2254.5) U1.H5@2518.71,2270.48 ; v2(2517,2254.5) U1.H5@2522.59,2270.03 ; v2(2517,2254.5) U1.H5@2518.71,2270.48 ; v2@2517.09,2255.91 U1.H5@2517.09,2268.85 ; v2@2517.09,2255.91 U1.H5@2522.5,2269.53 ; v2@2517.09,2255.91 U1.H5@2518.71,2270.48 ; U1.H5@2517.09,2268.85 U1.H5@2518.71,2270.48 ; v2@2518.71,2253.29 U1.H5@2518.71,2270.48 ; v2@2518.71,2253.29 U1.H5@2522.59,2270.03 ; v2@2518.71,2253.29 U1.H5@2518.71,2270.48 ; U1.H5@2518.71,2270.48 v2@2522.98,2254.98 ; U1.H5@2518.71,2270.48 v2@2522.98,2254.98 ; U1.H5@2518.71,2270.48 v2@2522.98,2254.98 ; U1.H5@2522.5,2269.53 2522.92,2253.53 U1.H5@2522.59,2270.03 ; v2@2534.5,2267.06 2534.5,2270 v2(2535,2270.5) v2@2534.5,2267.06
  Top w10: C47.1@1353,2756 C47.1@1356,2753 ; U1.P7@2446.33,2125.71 v2@2446.33,2142.03 ; U1.P7@2446.33,2125.71 v2@2446.33,2142.03 ; U1.P7@2446.33,2125.71 v2(2448.2,2143.9) ; U1.P7@2446.33,2125.71 v2(2448.2,2143.9) ; v2@2446.33,2142.03 v2(2448.2,2143.9) ; U1.N6@2446.33,2161.9 2448.2,2160.04 v2(2448.2,2143.9) ; U1.N6@2446.33,2161.9 v2(2448.2,2143.9) ; U1.N6@2446.33,2161.9 v2(2448.2,2143.9) ; U1.K5@2482.52,2234.29 U1.J5@2500.62,2252.38 U1.K5@2482.52,2234.29
  Top w11: U1.H5@2518.71,2270.48 v2(2535,2270.5) U1.H5@2518.71,2270.48
  Top w12: R17.1@1266.27,2756 v1(1318,2769) ; 1308.04,2756 R17.1@1262,2755 1263,2756 1353,2756 v1(1318,2769) ; v1(1318,2769) C47.1@1356,2753 1309.51,2756 v1(1318,2769) ; U1.J5@2500.62,2252.38 U1.H5@2518.71,2270.48 ; U1.J5@2500.62,2252.38 U1.H5@2518.71,2270.48 ; U1.J5@2500.62,2252.38 v2(2517,2254.5) ; U1.J5@2500.62,2252.38 v2(2517,2254.5) ; v2(2517,2254.5) U1.H5@2518.71,2270.48 ; v2(2517,2254.5) U1.H5@2518.71,2270.48
  Top w15: U22.G9@1717.54,2269.81 1738,2269.81 1770,2301.81 ; U22.C9@1717.54,2395.8 1745,2395.8 1755,2405.8 1755,2458.79 ; U22.A9@1717.54,2458 U22.A9@1717.54,2458.79 ; C124.1@1243,2223 v1(1214,2223) C124.1@1243,2223 ; C124.1@1243,2223 R350.1@1278,2223 C124.1@1243,2223 ; 1413.82,2269.81 1413.82,2216 1423,2206.82 ; 1413.82,2269.81 U22.G1@1465.57,2269.81 1413.82,2269.81 ; 1413.82,2269.81 1394.81,2269.81 v1(1387,2262) 1413.82,2269.81 ; 1415,2341 1424,2332 ; 1415,2341 v1(1415,2380) ; 1415,2341 v1(1415,2380) ; v1(1415,2380) 1430.8,2395.8 ; 1423,2206.82 U22.J1@1465.57,2206.82 1423,2206.82 ; 1424,2332 1464.76,2332 U22.E1@1465.57,2332.81 1424,2332 ; 1430.8,2395.8 U22.C1@1465.57,2395.8 1430.8,2395.8 ; C134.1@1445.57,1948 v2(1425,1948) C134.1@1448,1948 ; C134.1@1445.57,1948 1465.57,1968 ; C134.1@1445.57,1948 C134.1@1448,1948 ; C134.1@1448,1948 1465.57,1968 ; 1465.57,1968 U22.R1@1465.57,2017.85 1465.57,1968 ; U22.M9@1717.54,2112.33 U22.M9@1717.54,2115.54 ; U22.M9@1717.54,2112.33 v2(1729,2127) ; U22.M9@1717.54,2112.33 v2(1729,2127) ; U22.M9@1717.54,2115.54 v2(1729,2127) ; U22.M9@1717.54,2115.54 v2(1729,2127) ; U22.J9@1717.54,2206.82 v2@1744.82,2206.82 ; U22.J9@1717.54,2206.82 v2@1744.82,2206.82 ; U22.J9@1717.54,2206.82 v2(1745,2207) ; U22.J9@1717.54,2206.82 v2(1745,2207) ; U22.A9@1717.54,2458.79 1755,2458.79 ; U22.A9@1717.54,2458.79 1755,2458.79 ; v2@1744.82,2206.82 v2(1745,2207) ; 1755,2458.79 1785.21,2458.79 v2(1786,2458) 1755,2458.79 ; 1770,2301.81 v2(1770,2332) ; 1770,2301.81 v2(1770,2332) ; v2(1770,2332) 1769.19,2332.81 U22.E9@1717.54,2332.81 v2(1770,2332) ; v1(1445,2459) 1465.36,2459 U22.A1@1465.57,2458.79 v1(1445,2459) ; U22.G3@1528.56,2269.81 1548.19,2269.81 v2(1549,2269) U22.G3@1528.56,2269.81 ; U22.C3@1528.56,2395.8 1550.9,2395.8 v2(1551.2,2396.1) U22.C3@1528.56,2395.8 ; v2(1633,2402) 1653,2402 1654.55,2400.45 U22.C7@1654.55,2395.8 v2(1633,2402) ; v2(1634,2270) 1654.36,2270 U22.G7@1654.55,2269.81 v2(1634,2270)
  Top w20: U5.2@1341.42,2898 1355,2980.51 ; U5.2@1355,2896.89 1355,2980.51 ; 1355,3129 U5.2@1355,2889.02 ; C45.1@1355.55,2800 1356,2769 ; U5.2@1355.55,2889.02 U5.2@1355,2889.02 ; U5.2@1368.58,2898 1355,2980.51 ; U5.2@1355,2889.02 U5.2@1355.55,2888.46 ; C45.1@1355.55,2811 U5.2@1355.55,2888.46 ; C45.1@1355.55,2811 1356,2810.55 C45.1@1356,2801 ; C45.1@1355.55,2811 1355.55,2830 v1(1318,2830) C45.1@1355.55,2822 ; C45.1@1355.55,2811 1368.57,2879.93 C45.1@1355.55,2822 ; C45.1@1355.55,2811 1341.45,2879.71 C45.1@1355.55,2822 ; C45.1@1355.55,2811 1355,2881.14 C45.1@1355.55,2822 ; C45.1@1355.55,2811 v1(1318,2801) C45.1@1356,2801 ; C45.1@1355.55,2822 U5.2@1355.55,2888.46 ; C47.1@1356,2753 1356,2769 ; C47.1@1356,2753 1356,2769 ; C47.1@1356,2753 v1(1318,2769) 1356,2769 ; 1356,2769 C45.1@1356,2801
  Bottom w12: C76.1@2431,2045 2446.12,2060.12 2446.12,2063.89 2462.5,2080.27 2462.5,2121 ; 2462.5,2121 2447.9,2135.6 2447.9,2143.6 v2(2448.2,2143.9) 2462.5,2121 ; 2498,2273.5 v2(2517,2254.5) 2498,2273.5 ; 2498,2273.5 2498,2297 C75.1@2495.23,2299.77 2498,2273.5
  Bottom w15: C136.1@1851.55,2356 1852,2355.55 v1(1852,2312) ; C136.1@1860.97,2343.76 v1(1852,2312) ; v2(2010,2330) 2057,2377 R812.1@2149,2377 C820.1@2184,2377 ; v1(1336,2333) v1@1336.45,2333.45 ; v1(1336,2333) C73.1@1336.45,2390 v1@1336.45,2333.45 ; v1(1336,2333) 1345.9,2378.01 v1@1336.45,2333.45 ; v1(1336,2333) 1327,2378.01 v1@1336.45,2333.45 ; v1(1336,2333) 1336.45,2379 v1@1336.45,2333.45 ; v2(1633,2402) 1642,2402 ; v2(1633,2402) C130.1@1656,2388 ; v2(1633,2402) C130.1@1656,2388 ; v2(1633,2402) C130.1@1656,2388 ; v2(1633,2402) C130.1@1656,2388 ; 1642,2402 C130.1@1656,2388 ; 1642,2402 C130.1@1656,2388 ; 1642,2402 C130.1@1656,2388 ; 1645,2281 v2(1634,2270) C135.1@1645,2297 ; 1645,2281 C135.1@1645,2297 ; 1645,2281 C135.1@1645,2297 ; 1645,2281 C135.1@1645,2297 ; v1(1852,2312) 1842.17,2343.5 v1(1852,2312) ; v1(1852,2312) 1851.55,2345 v1(1852,2312) ; v1(1387,2262) C131.1@1416,2262 v1(1387,2262) ; v1(1415,2380) C140.1@1444,2380 v1(1415,2380) ; C133.1@1521,2269 v2(1549,2269) C133.1@1521,2269 ; v2(1551.2,2396.1) 1575.9,2396.1 C128.1@1576,2396 v2(1551.2,2396.1) ; C129.1@1723,2208 1744,2208 v2(1745,2207) C129.1@1723,2208 ; v2(1729,2127) 1745,2127 C132.1@1749,2123 v2(1729,2127) ; C138.1@1758,2458 v2(1786,2458) C138.1@1758,2458 ; C139.1@1770,2312 v2(1770,2332) C139.1@1770,2312
3.3EN_5-POWER0: C22.1 R6.2 U3.7 | length 742.9
  Top w4.5: U3.7@6873.23,1565.36 6883,1541.58 ; U3.7@6875.44,1597.97 6900,1619 ; U3.7@6877.58,1566.7 6883,1541.58 ; U3.7@6878.62,1594.75 6900,1619 ; C22.1@6879.25,1511.96 6883,1536.12 ; U3.7@6883,1567.28 6883,1541.58 ; U3.7@6883,1580.67 U3.7@6883,1579.39 ; U3.7@6883,1591.5 6900,1619 ; C22.1@6883.77,1511.68 6883,1536.12 ; U3.7@6887.87,1589.03 6900,1619 ; U3.7@6888.42,1566.7 6883,1541.58 ; C22.1@6890.16,1512.74 6883,1536.12 ; U3.7@6892.17,1587.63 6900,1619 ; U3.7@6892.77,1565.36 6883,1541.58 ; C22.1@6894.35,1514.46 6883,1536.12 ; R6.2@6988.1,1628.51 6966.34,1619 ; R6.2@6989.38,1613.27 6966.34,1619 ; R6.2@6989.51,1624.21 6966.34,1619 ; R6.2@6990.05,1617.75 6966.34,1619 ; R6.2@6991,1621 R6.2@6990,1621 ; 6883,1536.12 C22.1@6887,1512 6886,1513 6883,1513 U3.7@6883,1579.39 ; U3.7@6883,1579.39 6883,1602 6900,1619 ; 6900,1619 6989.89,1619 6989.89,1621 R6.2@6990,1621 ; 6966.34,1619 R6.2@6990,1621
3.3V_AUX1: C228.1 C229.1 J6.24 R418.2 | length 905
  Top w20: J6.24@3980.83,3556.81 v1@4117,3556.81 ; J6.24@4010.36,3556.81 4080.2,3556.81 v1(4095,3557) ; 4047,3556.81 v1(4119,3557) ; v1(4095,3557) v1@4117,3556.81 ; v1(4095,3557) 4023,3556.81 v1(4095,3557) ; v1(4095,3557) v1(4119,3557) ; v1@4117,3556.81 v1(4119,3557)
  Bottom w20: R418.2@4158.21,3657.2 4158.4,3657.01 C228.1@4158.4,3611 ; C229.1@4158.55,3566 C228.1@4158.4,3611 ; v1(4119,3557) 4157.55,3557 4158.55,3556 C229.1@4158.55,3555 ; v1(4119,3557) v1(4095,3557) v1(4119,3557) ; v1(4119,3557) C229.1@4158.55,3555 ; C229.1@4158.4,3555.15 C228.1@4158.4,3611 ; C229.1@4158.4,3555.15 C229.1@4158.55,3555 ; C229.1@4158.4,3555.15 C228.1@4158.4,3611 ; C228.1@4158.4,3611 4158.21,3655.2 C228.1@4158.4,3611
3.3V_FB_5-POWER0: C15.2 R9.2 R11.1 U3.5 | length 2791.8
  Top w4.5: C15.2@6757.27,1478.43 6762.85,1455.55 ; C15.2@6757.26,1478.6 R9.2@6759.72,1505.84 ; C15.2@6757.25,1479.23 6760.41,1455.41 ; C15.2@6757.27,1479.52 R9.2@6762.89,1505.62 ; R11.1@6757.31,1444.95 6764,1467.52 ; C15.2@6757.31,1478.05 6764,1455.47 ; C15.2@6757.3,1478.14 R11.1@6765,1444 ; R9.2@6757.36,1512.72 6765,1490.5 ; C15.2@6757.41,1477.43 R11.1@6768.23,1444.36 ; C15.2@6757.46,1480.81 6766.69,1502.67 ; C15.2@6757.68,1476.46 R11.1@6771.61,1448.09 ; C15.2@6757.69,1481.56 6769.37,1503.2 ; R9.2@6757.96,1517.24 6772.5,1539.55 ; R11.1@6761.75,1444.09 6764,1467.52 ; C15.2@6761.75,1478.85 R11.1@6765,1444 ; C15.2@6761.75,1478.91 6764,1455.47 ; C15.2@6761.75,1478.94 R9.2@6762.89,1505.62 ; C15.2@6761.75,1479.07 6762.85,1455.55 ; C15.2@6761.77,1479.4 6760.41,1455.41 ; R9.2@6761.76,1513.78 6765,1490.5 ; C15.2@6761.86,1478.16 R11.1@6771.61,1448.09 ; C15.2@6761.85,1479.79 6769.37,1503.2 ; R9.2@6761.94,1515.1 6772.5,1539.55 ; C15.2@6768.14,1478.16 6760.41,1455.41 ; C15.2@6768.15,1479.82 R9.2@6759.72,1505.84 ; R9.2@6768.17,1513.28 6772.5,1539.55 ; C15.2@6768.21,1478.48 6762.85,1455.55 ; C15.2@6768.21,1479.52 R11.1@6771.61,1448.09 ; C15.2@6768.25,1478.85 R11.1@6765,1444 ; C15.2@6768.25,1478.99 6766.69,1502.67 ; C15.2@6768.25,1479.15 R11.1@6768.23,1444.36 ; R9.2@6768.24,1513.78 6765,1490.5 ; C15.2@6772.27,1476.31 6760.41,1455.41 ; C15.2@6772.32,1481.56 R9.2@6759.72,1505.84 ; C15.2@6772.5,1477.03 6762.85,1455.55 ; C15.2@6772.56,1480.73 R9.2@6762.89,1505.62 ; R11.1@6772.58,1445.6 6764,1467.52 ; C15.2@6772.58,1477.4 6764,1455.47 ; R9.2@6772.64,1512.72 6765,1490.5 ; R9.2@6772.67,1512.92 6772.5,1539.55 ; C15.2@6772.7,1478.14 R11.1@6765,1444 ; U3.5@6773.24,1569.22 6772.5,1539.94 ; U3.5@6777.75,1568.76 6772.5,1539.94 ; U3.5@6783,1567.28 6772.5,1539.94 ; U3.5@6783,1580.67 6778,1572.5 6772.5,1567 6772.5,1516 6766,1516 R9.2@6764,1514 ; U3.5@6787.89,1564.86 6772.5,1539.94 ; U3.5@6791.55,1562.19 6772.5,1539.94 ; C15.2@6757.5,1477.04 6764,1467.52 ; C15.2@6757.5,1477.04 6764,1467.52 ; C15.2@6757.5,1477.04 6764,1467.52 ; C15.2@6757.5,1477.04 6764,1467.52 ; C15.2@6757.5,1477.04 6764,1467.52 ; C15.2@6757.7,1481.61 6765,1490.5 ; C15.2@6757.7,1481.61 6765,1490.5 ; C15.2@6757.7,1481.61 6765,1490.5 ; C15.2@6757.7,1481.61 6765,1490.5 ; C15.2@6757.7,1481.61 6765,1490.5 ; R9.2@6759.72,1505.84 6761.78,1478.56 R11.1@6768.23,1444.36 ; R9.2@6759.72,1505.84 C15.2@6765,1479 ; 6760.41,1455.41 C15.2@6765,1479 ; C15.2@6761.75,1478.82 6764,1467.52 ; C15.2@6761.75,1478.82 6764,1467.52 ; C15.2@6761.75,1478.82 6764,1467.52 ; C15.2@6761.75,1478.82 6764,1467.52 ; C15.2@6761.75,1478.82 6764,1467.52 ; C15.2@6761.78,1479.46 6765,1490.5 ; C15.2@6761.78,1479.46 6765,1490.5 ; C15.2@6761.78,1479.45 6766.69,1502.67 ; C15.2@6761.78,1479.46 6765,1490.5 ; C15.2@6761.78,1479.46 6765,1490.5 ; C15.2@6761.78,1479.46 6765,1490.5 ; 6762.85,1455.55 C15.2@6765,1479 ; R9.2@6762.89,1505.62 C15.2@6768.22,1479.45 ; R9.2@6762.89,1505.62 C15.2@6765,1479 ; 6764,1455.47 6768.23,1478.64 6769.37,1503.2 ; 6764,1455.47 C15.2@6765,1479 ; 6764,1467.52 R11.1@6768.23,1444.36 ; 6764,1467.52 R11.1@6765,1444 ; 6764,1467.52 C15.2@6772.04,1475.77 ; 6764,1467.52 C15.2@6768.17,1478.26 ; 6764,1467.52 C15.2@6765,1479 ; 6764,1467.52 C15.2@6772.04,1475.77 ; 6764,1467.52 C15.2@6768.17,1478.26 ; 6764,1467.52 C15.2@6765,1479 ; 6764,1467.52 C15.2@6772.04,1475.77 ; 6764,1467.52 C15.2@6768.17,1478.26 ; 6764,1467.52 C15.2@6765,1479 ; 6764,1467.52 C15.2@6772.04,1475.77 ; 6764,1467.52 C15.2@6768.17,1478.26 ; 6764,1467.52 C15.2@6765,1479 ; 6764,1467.52 C15.2@6772.04,1475.77 ; 6764,1467.52 C15.2@6768.17,1478.26 ; 6764,1467.52 C15.2@6765,1479 ; R9.2@6764,1514 R9.2@6765,1514 ; R9.2@6764,1514 6765,1513 C15.2@6765,1479 ; R11.1@6765,1444 6764,1444 6764,1478 C15.2@6765,1479 ; R11.1@6765,1444 C15.2@6765,1479 ; C15.2@6765,1479 6769.37,1503.2 ; C15.2@6765,1479 6765,1490.5 ; C15.2@6765,1479 6765,1490.5 ; C15.2@6765,1479 6766.69,1502.67 ; C15.2@6765,1479 6765,1490.5 ; C15.2@6765,1479 6765,1490.5 ; C15.2@6765,1479 R11.1@6771.61,1448.09 ; C15.2@6765,1479 R11.1@6768.23,1444.36 ; 6765,1490.5 R9.2@6765,1514 ; 6765,1490.5 C15.2@6772.3,1481.61 ; 6765,1490.5 C15.2@6768.22,1479.46 ; 6765,1490.5 C15.2@6772.3,1481.61 ; 6765,1490.5 C15.2@6768.22,1479.46 ; 6765,1490.5 C15.2@6772.3,1481.61 ; 6765,1490.5 C15.2@6768.22,1479.46 ; 6765,1490.5 C15.2@6772.3,1481.61 ; 6765,1490.5 C15.2@6768.22,1479.46 ; 6765,1490.5 C15.2@6772.3,1481.61 ; 6765,1490.5 C15.2@6768.22,1479.46 ; 6765,1502.5 6757.36,1480.28 6765,1502.5 ; 6765,1502.5 6772.64,1480.28 6765,1502.5 ; 6765,1502.5 6761.76,1479.22 6765,1502.5 ; 6765,1502.5 6768.24,1479.22 6765,1502.5 ; R9.2@6765,1514 6772.5,1539.55 ; 6766.69,1502.67 6772.72,1479.72 R11.1@6771.61,1448.09 ; R11.1@6768.23,1444.36 6772.75,1478.86 6769.37,1503.2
